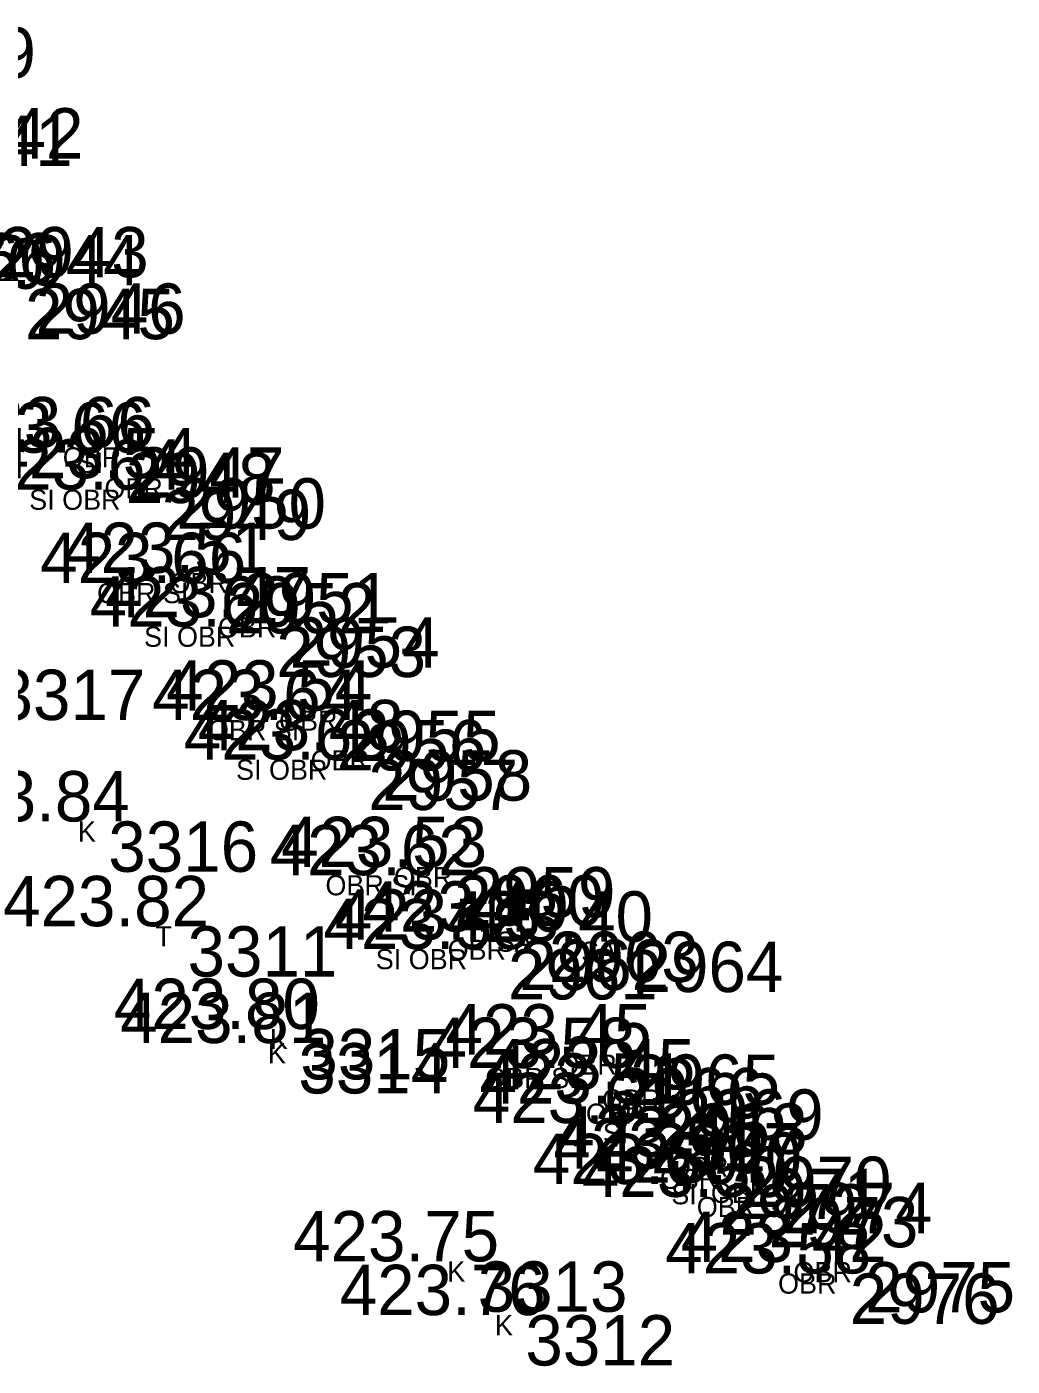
# Model space of a CAD drawing. Extents: x -639390 to -639075, y -1138747 to -1138358.
# Drawn here: x -639236.52 to -639221.84, y -1138483.6 to -1138463.66 of the extents above; entities that cross this region are included whole.
import ezdxf

# ---------------------------------------------------------------- set-up
doc = ezdxf.new("R2010")
doc.units = 0
for name, color, linetype in [('Vrstva 11', 7, 'Continuous'), ('Vrstva 12', 7, 'Continuous'), ('Vrstva 13', 7, 'Continuous'), ('Vrstva 57', 7, 'Continuous')]:
    doc.layers.add(name, color=color, linetype=linetype)

msp = doc.modelspace()

# ---------------------------------------------------------------- linework, layer by layer
at = {"layer": 'Vrstva 11'}
for p, q in [((-639235.19, -1138469.92), (-639235.19, -1138469.92)), ((-639235.32, -1138470), (-639235.32, -1138470)), ((-639234.79, -1138470.55), (-639234.79, -1138470.55)), ((-639234.57, -1138470.38), (-639234.57, -1138470.38)), ((-639233.83, -1138471.94), (-639233.83, -1138471.94)), ((-639233.6, -1138471.79), (-639233.6, -1138471.79)), ((-639232.88, -1138472.45), (-639232.88, -1138472.45)), ((-639233.08, -1138472.59), (-639233.08, -1138472.59)), ((-639231.97, -1138473.84), (-639231.97, -1138473.84)), ((-639232.18, -1138473.98), (-639232.18, -1138473.98)), ((-639231.5, -1138474.43), (-639231.5, -1138474.43)), ((-639231.71, -1138474.57), (-639231.71, -1138474.57)), ((-639235.58, -1138475.49), (-639235.58, -1138475.49)), ((-639230.43, -1138476.29), (-639230.43, -1138476.29)), ((-639230.26, -1138476.17), (-639230.26, -1138476.17)), ((-639234.4, -1138477.05), (-639234.4, -1138477.05)), ((-639229.02, -1138477.13), (-639229.02, -1138477.13)), ((-639229.46, -1138477.25), (-639229.46, -1138477.25)), ((-639227.76, -1138477.28), (-639227.76, -1138477.28)), ((-639229.63, -1138477.39), (-639229.63, -1138477.39)), ((-639232.72, -1138478.58), (-639232.72, -1138478.58)), ((-639232.75, -1138478.79), (-639232.75, -1138478.79)), ((-639227.81, -1138478.96), (-639227.81, -1138478.96)), ((-639228.05, -1138479.16), (-639228.05, -1138479.16)), ((-639227.16, -1138479.48), (-639227.16, -1138479.48)), ((-639227.4, -1138479.69), (-639227.4, -1138479.69)), ((-639227.5, -1138479.98), (-639227.5, -1138479.98)), ((-639226.15, -1138480.48), (-639226.15, -1138480.48)), ((-639226.3, -1138480.66), (-639226.3, -1138480.66)), ((-639226.48, -1138480.89), (-639226.48, -1138480.89)), ((-639225.54, -1138480.87), (-639225.54, -1138480.87)), ((-639225.75, -1138481.08), (-639225.75, -1138481.08)), ((-639230.08, -1138482.04), (-639230.08, -1138482.04)), ((-639224.31, -1138482.05), (-639224.31, -1138482.05)), ((-639224.54, -1138482.22), (-639224.54, -1138482.22)), ((-639229.37, -1138482.84), (-639229.37, -1138482.84))]:
    msp.add_line(p, q, dxfattribs=at)

# ---------------------------------------------------------------- texts
at = {"layer": 'Vrstva 12'}
for s, p in [('423.66 ', (-639239.146, -1138467.48)), ('423.70 ', (-639239.319, -1138467.56)), ('423.66 ', (-639237.676, -1138469.92)), ('423.66 ', (-639237.806, -1138470)), ('423.54 ', (-639237.039, -1138470.38)), ('423.64 ', (-639237.259, -1138470.55)), ('423.51 ', (-639235.975, -1138471.79)), ('423.66 ', (-639236.316, -1138471.94)), ('423.47 ', (-639235.349, -1138472.45)), ('423.60 ', (-639235.579, -1138472.59)), ('423.54 ', (-639234.439, -1138473.84)), ('423.64 ', (-639234.649, -1138473.98)), ('423.48 ', (-639233.969, -1138474.43)), ('423.63 ', (-639234.179, -1138474.57)), ('423.84 ', (-639238.049, -1138475.49)), ('423.62 ', (-639232.899, -1138476.29)), ('423.53 ', (-639232.729, -1138476.17)), ('423.82 ', (-639236.869, -1138477.05)), ('423.45 ', (-639231.93, -1138477.25)), ('423.40 ', (-639231.519, -1138477.13)), ('423.40 ', (-639230.259, -1138477.28)), ('423.58 ', (-639232.099, -1138477.39)), ('423.80 ', (-639235.219, -1138478.58)), ('423.81 ', (-639235.125, -1138478.79)), ('423.45 ', (-639230.28, -1138478.96)), ('423.58 ', (-639230.519, -1138479.16)), ('423.45 ', (-639229.63, -1138479.48)), ('423.51 ', (-639229.775, -1138479.69)), ('423.61 ', (-639229.875, -1138479.98)), ('423.45 ', (-639228.62, -1138480.48)), ('423.51 ', (-639228.675, -1138480.66)), ('423.40 ', (-639228.039, -1138480.87)), ('423.60 ', (-639228.979, -1138480.89)), ('423.50 ', (-639228.249, -1138481.08)), ('423.75 ', (-639232.55, -1138482.04)), ('423.42 ', (-639226.779, -1138482.05)), ('423.58 ', (-639227.009, -1138482.22)), ('423.76 ', (-639231.856, -1138482.84))]:
    msp.add_text(s, height=0.75, dxfattribs=at).set_placement(p)
at = {"layer": 'Vrstva 13'}
for s, p in [(' 2939', (-639238.89, -1138464.42)), (' 2941', (-639238.34, -1138465.73)), (' 2942', (-639238.18, -1138465.62)), (' 2944', (-639237.33, -1138467.51)), (' 2943', (-639237.21, -1138467.39)), (' 2945', (-639236.82, -1138468.31)), (' 2946', (-639236.66, -1138468.23)), (' 2947', (-639235.19, -1138470.67)), (' 2948', (-639235.32, -1138470.75)), (' 2949', (-639234.79, -1138471.3)), (' 2950', (-639234.57, -1138471.13)), (' 2952', (-639233.83, -1138472.69)), (' 2951', (-639233.6, -1138472.54)), (' 2954', (-639232.88, -1138473.2)), (' 2953', (-639233.08, -1138473.34)), (' 3317', (-639237.26, -1138473.98)), (' 2955', (-639231.97, -1138474.59)), (' 2956', (-639232.18, -1138474.73)), (' 2958', (-639231.5, -1138475.18)), (' 2957', (-639231.71, -1138475.32)), (' 3316', (-639235.58, -1138476.24)), (' 2960', (-639230.43, -1138477.04)), (' 2959', (-639230.26, -1138476.92)), (' 3311', (-639234.4, -1138477.8)), (' 2963', (-639229.02, -1138477.88)), (' 2962', (-639229.46, -1138478)), (' 2964', (-639227.76, -1138478.03)), (' 2961', (-639229.63, -1138478.14)), (' 3315', (-639232.72, -1138479.33)), (' 3314', (-639232.75, -1138479.54)), (' 2965', (-639227.81, -1138479.71)), (' 2966', (-639228.05, -1138479.91)), (' 2969', (-639227.16, -1138480.23)), (' 2968', (-639227.4, -1138480.44)), (' 2967', (-639227.5, -1138480.73)), (' 2970', (-639226.15, -1138481.23)), (' 2971', (-639226.3, -1138481.41)), (' 2972', (-639226.48, -1138481.64)), (' 2974', (-639225.54, -1138481.62)), (' 2973', (-639225.75, -1138481.83)), (' 3313', (-639230.08, -1138482.79)), (' 2975', (-639224.31, -1138482.8)), (' 2976', (-639224.54, -1138482.97)), (' 3312', (-639229.37, -1138483.59))]:
    msp.add_text(s, height=0.75, dxfattribs=at).set_placement(p)
at = {"layer": 'Vrstva 57'}
for s, p in [('OBR', (-639235.979, -1138470.22)), ('SI', (-639235.758, -1138470.3)), ('SI OBR', (-639236.479, -1138470.85)), ('OBR', (-639235.359, -1138470.68)), ('OBR SI', (-639235.468, -1138472.24)), ('OBR', (-639234.389, -1138472.09)), ('OBR', (-639233.669, -1138472.75)), ('SI OBR', (-639234.769, -1138472.89)), ('OBR', (-639232.759, -1138474.14)), ('OBR SI', (-639233.818, -1138474.28)), ('OBR', (-639232.289, -1138474.73)), ('SI OBR', (-639233.399, -1138474.87)), ('K', (-639235.755, -1138475.79)), ('OBR SI', (-639232.068, -1138476.59)), ('OBR', (-639231.049, -1138476.47)), ('T', (-639234.6, -1138477.35)), ('SA', (-639229.52, -1138477.43)), ('OBR', (-639230.249, -1138477.55)), ('SA', (-639228.26, -1138477.58)), ('SI OBR', (-639231.319, -1138477.69)), ('K', (-639232.895, -1138478.88)), ('K', (-639232.925, -1138479.09)), ('OBR', (-639228.599, -1138479.26)), ('OBR SI', (-639229.688, -1138479.46)), ('OBR', (-639227.949, -1138479.78)), ('OBR', (-639228.189, -1138479.99)), ('SI', (-639227.938, -1138480.28)), ('OBR', (-639226.939, -1138480.78)), ('OBR', (-639227.089, -1138480.96)), ('SI', (-639226.918, -1138481.19)), ('OBR', (-639226.329, -1138481.17)), ('OBR', (-639226.539, -1138481.38)), ('K', (-639230.255, -1138482.34)), ('OBR', (-639225.099, -1138482.35)), ('OBR', (-639225.329, -1138482.52)), ('K', (-639229.545, -1138483.14))]:
    msp.add_text(s, height=0.3, dxfattribs=at).set_placement(p)

doc.saveas('drawing.dxf')
